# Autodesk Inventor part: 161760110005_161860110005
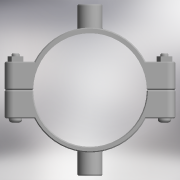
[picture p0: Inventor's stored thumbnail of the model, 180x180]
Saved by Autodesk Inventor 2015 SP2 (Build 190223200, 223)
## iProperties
Created: 2017-05
Part Number: 161760110005_161860110005
Material: Generic
Description: PLASSON DOUBLE SADDLE 110-1/2"
Document SubType Name: Modeling
Designer: KIM
Density: 1 g/cm^3
Appearance: Default
Author: KIM
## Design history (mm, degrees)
derived "16176.ipt"
feature "Solid1::16176.ipt"
feature "Solid2::16176.ipt"
tag "TaggingFeature1"
body "Solid1"
body "Solid2"
other parameters: "d0" = 121, "d1" = 165, "d2" = 55, "d4" = 116, "d5" = 0, "d6" = 8.25, "d7" = 165, "d8" = 0.1, "d10" = 0, "d11" = 1.1, "d20" = 1.1, "d23" = 1.1, "d36" = 13, "d37" = 10.4, "d38" = 63, "d39" = 0, "d40" = 3, "d41" = 5, "d42" = 0, "d43" = 8, "d44" = 3, "d45" = 0, "d46" = 1.1, "d52" = 18.631, "d53" = 18, "d54" = 0, "d55" = 16, "d57" = 0, "d58" = 118.8, "d60" = 0, "d62" = 13, "d63" = 10.4, "d66" = 95.2, "d67" = 166, "d68" = 24.2203, "d69" = 18.631, "d70" = 18, "d71" = 0, "d72" = 16, "d74" = 0, "d75" = 1.1, "B_" = 16, "G_" = 18.631, "A_" = 83, "L_" = 165, "L_1" = 116, "l_2" = 18
